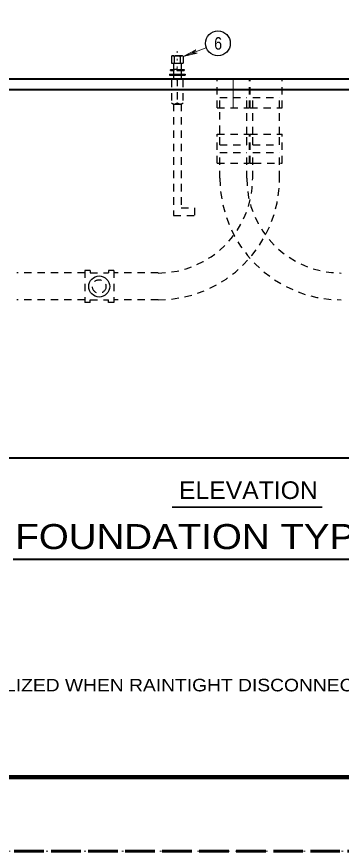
# Model space of a CAD drawing. Extents: x 312583 to 312854, y 144419 to 144597.
# Drawn here: x 312746.6 to 312766.3, y 144418.6 to 144469.3 of the extents above; entities that cross this region are included whole.
import ezdxf
from ezdxf.enums import TextEntityAlignment as Align

# ---------------------------------------------------------------- set-up
doc = ezdxf.new("R2010")
doc.units = 0
doc.header["$LTSCALE"] = 0.3
for name, pattern in [('DOTTED', [1.5, 0.3, -1.2]), ('LONG_DASHED', [7.5, 6, -1.5]), ('SHORT_DASHED', [2.7, 1.5, -1.2])]:
    doc.linetypes.add(name, pattern=pattern)
for name, color, linetype, lineweight in [('1', 7, 'Continuous', 25), ('2', 7, 'Continuous', 13), ('63', 7, 'DOTTED', 13)]:
    doc.layers.add(name, color=color, linetype=linetype, lineweight=lineweight)

msp = doc.modelspace()

# ---------------------------------------------------------------- linework, layer by layer
at = {"layer": '1', "linetype": 'DOTTED', "lineweight": 13}
msp.add_line((312756.3646, 144467.1658), (312756.3646, 144465.4868), dxfattribs=at)
at = {"layer": '1'}
for p, q in [((312756.0042, 144466.8438), (312756.0042, 144466.4451)), ((312756.0962, 144466.8975), (312756.6329, 144466.8975)), ((312756.1806, 144466.8438), (312756.1806, 144466.4451)), ((312756.5409, 144466.8438), (312756.5409, 144466.4451)), ((312756.7249, 144466.8438), (312756.7249, 144466.4451)), ((312755.9506, 144466.0541), (312755.9506, 144465.9928)), ((312756.0042, 144466.4451), (312756.7249, 144466.4451)), ((312756.1269, 144466.4451), (312756.1269, 144465.4868)), ((312756.3262, 144465.9928), (312756.7786, 144465.9928)), ((312756.3492, 144466.0541), (312756.7786, 144466.0541)), ((312756.6022, 144466.4451), (312756.6022, 144465.4868)), ((312756.7786, 144466.0541), (312756.7786, 144465.9928)), ((312755.8892, 144465.7705), (312756.8322, 144465.7705)), ((312755.8892, 144465.7705), (312755.8892, 144465.7168)), ((312755.8892, 144465.7551), (312756.8322, 144465.7551)), ((312755.8892, 144465.7398), (312756.8322, 144465.7398)), ((312755.8892, 144465.7245), (312756.8322, 144465.7245)), ((312755.8892, 144465.7168), (312756.8322, 144465.7168)), ((312756.1269, 144465.4868), (312756.6022, 144465.4868)), ((312756.1882, 144465.4868), (312756.5409, 144465.4868)), ((312756.8322, 144465.7705), (312756.8322, 144465.7168))]:
    msp.add_line(p, q, dxfattribs=at)
at = {"layer": '1', "lineweight": 40}
for p, q in [((312724.8622, 144465.4868), (312790.0289, 144465.4868)), ((312728.8566, 144465.4868), (312794.0232, 144465.4868)), ((312744.5732, 144464.8505), (312772.1962, 144464.8505)), ((312728.2202, 144442.4868), (312794.6672, 144442.4868))]:
    msp.add_line(p, q, dxfattribs=at)
at = {"layer": '1', "linetype": 'SHORT_DASHED'}
for p, q in [((312756.3646, 144465.4868), (312756.3646, 144463.9611)), ((312758.7872, 144463.7311), (312758.7872, 144465.4868)), ((312760.7422, 144463.7311), (312760.7422, 144465.4868)), ((312760.7882, 144463.7311), (312760.7882, 144465.4868)), ((312762.7356, 144463.7311), (312762.7356, 144465.4868)), ((312756.0119, 144465.4255), (312756.0119, 144464.0225)), ((312756.7096, 144465.4255), (312756.7096, 144464.0225)), ((312756.1269, 144463.9688), (312756.1269, 144457.1838)), ((312756.1882, 144463.9611), (312756.5409, 144463.9611)), ((312756.6022, 144463.9688), (312756.6022, 144457.6591)), ((312758.9482, 144464.3675), (312760.5812, 144464.3675)), ((312758.9482, 144463.7311), (312758.9482, 144464.3675)), ((312760.5812, 144463.7311), (312760.5812, 144464.3675)), ((312760.9492, 144464.3675), (312762.5746, 144464.3675)), ((312760.9492, 144463.7311), (312760.9492, 144464.3675)), ((312762.5746, 144463.7311), (312762.5746, 144464.3675)), ((312758.7872, 144463.7311), (312760.7422, 144463.7311)), ((312760.5812, 144462.1365), (312760.5812, 144463.7311)), ((312760.7882, 144463.7311), (312762.7356, 144463.7311)), ((312760.9492, 144462.1365), (312760.9492, 144463.7311)), ((312762.5746, 144462.1365), (312762.5746, 144463.7311)), ((312758.7872, 144460.3731), (312758.7872, 144462.1365)), ((312758.7872, 144462.1365), (312760.7422, 144462.1365)), ((312758.9482, 144461.4925), (312758.9482, 144462.1365)), ((312760.5812, 144461.4925), (312760.5812, 144462.1365)), ((312760.7422, 144460.3731), (312760.7422, 144462.1365)), ((312760.7422, 144462.1058), (312760.7422, 144462.1365)), ((312760.7882, 144460.3731), (312760.7882, 144462.1365)), ((312760.7882, 144462.1365), (312762.7356, 144462.1365)), ((312760.9492, 144461.4925), (312760.9492, 144462.1365)), ((312762.5746, 144461.4925), (312762.5746, 144462.1365)), ((312758.9482, 144461.4925), (312760.5812, 144461.4925)), ((312760.9492, 144461.4925), (312762.5746, 144461.4925)), ((312758.9482, 144461.0171), (312760.5812, 144461.0171)), ((312758.9482, 144459.4531), (312758.9482, 144461.0171)), ((312760.5812, 144459.4531), (312760.5812, 144461.0171)), ((312760.9492, 144461.0171), (312762.5746, 144461.0171)), ((312760.9492, 144459.4531), (312760.9492, 144461.0171)), ((312762.5746, 144459.4531), (312762.5746, 144461.0171)), ((312758.7872, 144460.3731), (312760.7422, 144460.3731)), ((312756.1269, 144457.1838), (312757.3996, 144457.1838)), ((312750.7526, 144453.8565), (312750.7526, 144451.9091)), ((312751.0746, 144453.8565), (312750.7526, 144453.8565)), ((312751.0746, 144453.8565), (312751.0746, 144453.7031)), ((312752.1862, 144453.8565), (312752.1862, 144453.7031)), ((312752.5082, 144453.8565), (312752.1862, 144453.8565)), ((312752.5082, 144453.8565), (312752.5082, 144451.9091)), ((312750.7526, 144453.7031), (312746.6049, 144453.7031)), ((312751.0746, 144453.7031), (312752.1862, 144453.7031)), ((312755.1992, 144453.7031), (312752.5082, 144453.7031)), ((312750.7526, 144452.0701), (312746.6049, 144452.0701)), ((312751.0746, 144451.9091), (312750.7526, 144451.9091)), ((312751.0746, 144451.9091), (312751.0746, 144452.0701)), ((312751.0746, 144452.0701), (312752.1862, 144452.0701)), ((312752.1862, 144451.9091), (312752.1862, 144452.0701)), ((312752.5082, 144451.9091), (312752.1862, 144451.9091)), ((312755.1992, 144452.0701), (312752.5082, 144452.0701))]:
    msp.add_line(p, q, dxfattribs=at)
at = {"layer": '1', "lineweight": 158}
msp.add_line((312616.5, 144423.0846), (312849, 144423.0846), dxfattribs=at)
at = {"layer": '1', "linetype": 'LONG_DASHED', "lineweight": 60}
msp.add_line((312851.75, 144418.5846), (312583.526, 144418.5846), dxfattribs=at)
at = {"layer": '1'}
for points in [[(312756.1192, 144466.8975), (312756.3186, 144466.8975), (312756.2802, 144466.8898), (312756.2572, 144466.8821), (312756.2266, 144466.8668), (312756.1882, 144466.8438), (312756.1729, 144466.8668), (312756.1576, 144466.8821), (312756.1269, 144466.8975), (312756.3032, 144466.8975), (312756.2496, 144466.8821), (312756.2112, 144466.8668), (312756.1882, 144466.8515), (312756.1576, 144466.8745), (312756.1346, 144466.8898), (312756.2802, 144466.8898), (312756.2266, 144466.8745), (312756.1882, 144466.8515), (312756.1499, 144466.8898), (312756.2649, 144466.8898), (312756.1882, 144466.8591), (312756.1576, 144466.8898), (312756.2496, 144466.8898), (312756.1806, 144466.8668), (312756.1652, 144466.8821), (312756.2342, 144466.8821), (312756.1882, 144466.8668), (312756.1729, 144466.8821), (312756.2189, 144466.8821), (312756.1882, 144466.8745), (312756.1806, 144466.8821), (312756.2036, 144466.8821), (312756.1882, 144466.8745)], [(312756.6099, 144466.8975), (312756.4106, 144466.8975), (312756.4412, 144466.8898), (312756.4642, 144466.8821), (312756.5026, 144466.8668), (312756.5409, 144466.8438), (312756.5562, 144466.8668), (312756.5716, 144466.8821), (312756.6022, 144466.8975), (312756.4259, 144466.8975), (312756.4719, 144466.8821), (312756.5102, 144466.8668), (312756.5409, 144466.8515), (312756.5716, 144466.8745), (312756.5869, 144466.8898), (312756.4489, 144466.8898), (312756.4949, 144466.8745), (312756.5409, 144466.8515), (312756.5792, 144466.8898), (312756.4642, 144466.8898), (312756.5409, 144466.8591), (312756.5716, 144466.8898), (312756.4719, 144466.8898), (312756.5409, 144466.8668), (312756.5639, 144466.8821), (312756.4872, 144466.8821), (312756.5409, 144466.8668), (312756.5562, 144466.8821), (312756.5102, 144466.8821), (312756.5409, 144466.8745), (312756.5486, 144466.8821), (312756.5256, 144466.8821), (312756.5409, 144466.8745)], [(312755.9506, 144466.0541), (312756.3646, 144466.1078), (312756.3262, 144465.9928)], [(312756.1269, 144465.9928), (312755.9506, 144466.0005), (312755.9582, 144466.0465), (312756.3492, 144466.1001), (312756.3416, 144466.0541), (312756.1192, 144466.0235), (312756.1192, 144466.0005), (312755.9582, 144466.0081), (312755.9582, 144466.0388), (312756.3416, 144466.0925), (312756.3339, 144466.0618), (312756.1116, 144466.0235), (312756.1116, 144466.0081), (312755.9659, 144466.0158), (312755.9659, 144466.0311), (312756.3262, 144466.0848), (312756.3262, 144466.0695), (312756.1116, 144466.0311), (312756.1039, 144466.0235), (312756.0579, 144466.0158), (312755.9736, 144466.0235), (312756.3186, 144466.0771), (312756.0272, 144466.0235)], [(312756.3492, 144466.0541), (312755.9506, 144465.9928), (312756.1269, 144465.9928)], [(312756.3416, 144466.0005), (312756.7709, 144466.0005), (312756.7709, 144466.0465), (312756.3492, 144466.0465), (312756.3416, 144466.0081), (312756.7632, 144466.0081), (312756.7632, 144466.0388), (312756.3569, 144466.0311), (312756.3492, 144466.0158), (312756.7556, 144466.0158), (312756.7479, 144466.0311), (312756.7479, 144466.0311), (312756.3569, 144466.0311), (312756.3569, 144466.0235), (312756.7479, 144466.0235)]]:
    msp.add_lwpolyline(points, dxfattribs=at)
at = {"layer": '1', "linetype": 'SHORT_DASHED'}
for points in [[(312756.2342, 144465.4868), (312756.4949, 144465.4868), (312756.4642, 144465.4791), (312756.4336, 144465.4715), (312756.4106, 144465.4561), (312756.3876, 144465.4485), (312756.3646, 144465.4331), (312756.3646, 144465.4255), (312756.3186, 144465.4638), (312756.2726, 144465.4791), (312756.2496, 144465.4868), (312756.4719, 144465.4868), (312756.4566, 144465.4791), (312756.4336, 144465.4791), (312756.4106, 144465.4638), (312756.3799, 144465.4485), (312756.3722, 144465.4408), (312756.3646, 144465.4331), (312756.3186, 144465.4638), (312756.2726, 144465.4791), (312756.4412, 144465.4791), (312756.4029, 144465.4638), (312756.3646, 144465.4408), (312756.2879, 144465.4791), (312756.4259, 144465.4791), (312756.3646, 144465.4408), (312756.3032, 144465.4715), (312756.4106, 144465.4791), (312756.3646, 144465.4485), (312756.3262, 144465.4715), (312756.3952, 144465.4715), (312756.3646, 144465.4638), (312756.3262, 144465.4715), (312756.3492, 144465.4561), (312756.3569, 144465.4715), (312756.3569, 144465.4485), (312756.3799, 144465.4638), (312756.3876, 144465.4638), (312756.3952, 144465.4715)], [(312756.2342, 144463.9611), (312756.4949, 144463.9611), (312756.4642, 144463.9688), (312756.4336, 144463.9765), (312756.4106, 144463.9918), (312756.3876, 144463.9995), (312756.3646, 144464.0148), (312756.3646, 144464.0225), (312756.3186, 144463.9841), (312756.2726, 144463.9688), (312756.2496, 144463.9688), (312756.4719, 144463.9611), (312756.4566, 144463.9688), (312756.4336, 144463.9688), (312756.4106, 144463.9841), (312756.3799, 144463.9995), (312756.3722, 144464.0071), (312756.3646, 144464.0148), (312756.3186, 144463.9841), (312756.2726, 144463.9688), (312756.4412, 144463.9688), (312756.4029, 144463.9841), (312756.3646, 144464.0071), (312756.2879, 144463.9688), (312756.4259, 144463.9688), (312756.3646, 144464.0071), (312756.3032, 144463.9765), (312756.4106, 144463.9688), (312756.3646, 144463.9995), (312756.3262, 144463.9765), (312756.3952, 144463.9765), (312756.3646, 144463.9841), (312756.3262, 144463.9841), (312756.3492, 144463.9918), (312756.3569, 144463.9765), (312756.3569, 144463.9995), (312756.3799, 144463.9841), (312756.3876, 144463.9841), (312756.3952, 144463.9765)], [(312758.9482, 144462.1365), (312758.9482, 144462.2131), (312758.9482, 144463.7311)], [(312760.7882, 144460.3731), (312761.0106, 144460.3731), (312762.7356, 144460.3731), (312762.7356, 144462.1365)], [(312756.6022, 144457.6591), (312757.3996, 144457.6591), (312757.3996, 144457.1838)]]:
    msp.add_lwpolyline(points, dxfattribs=at)
at = {"layer": '1'}
msp.add_circle((312751.6189, 144452.8815), 0.6389, dxfattribs=at)
at = {"layer": '1', "linetype": 'SHORT_DASHED'}
msp.add_circle((312751.6189, 144452.8815), 0.4108, dxfattribs=at)
at = {"layer": '1'}
for centre, radius, start, end in [((312756.094, 144466.7979), 0.0993, 25.60064, 154.39936), ((312756.3627, 144466.5846), 0.3126, 55.04559, 124.95441), ((312756.6313, 144466.7979), 0.0993, 25.60064, 154.39936)]:
    msp.add_arc(centre, radius, start, end, dxfattribs=at)
at = {"layer": '1', "linetype": 'SHORT_DASHED'}
for centre, radius, start, end in [((312756.1878, 144465.2153), 0.272, 50.00693, 129.99306), ((312756.5374, 144465.2153), 0.272, 50.00694, 129.99307), ((312756.1878, 144464.2327), 0.272, 230.00694, 309.99307), ((312756.5374, 144464.2327), 0.272, 230.00693, 309.99306), ((312755.1973, 144459.4499), 5.75, 270, 0), ((312755.1973, 144459.4499), 7.3792, 270, 0), ((312766.3293, 144459.4499), 7.3792, 180, 270), ((312766.3293, 144459.4499), 5.75, 180, 270)]:
    msp.add_arc(centre, radius, start, end, dxfattribs=at)
at = {"layer": '2'}
for p, q in [((312758.1279, 144467.3805), (312756.7249, 144466.8438)), ((312756.7249, 144466.8438), (312757.4916, 144467.2501)), ((312756.7249, 144466.8438), (312757.5682, 144467.0508)), ((312757.4916, 144467.2501), (312757.2692, 144467.0508)), ((312757.5682, 144467.0508), (312757.2692, 144467.0508)), ((312759.7686, 144463.7311), (312759.7686, 144465.4868))]:
    msp.add_line(p, q, dxfattribs=at)
at = {"layer": '2', "lineweight": 35}
msp.add_line((312756.0473, 144439.4857), (312765.163, 144439.4857), dxfattribs=at)
at = {"layer": '2', "lineweight": 40}
msp.add_line((312746.3902, 144436.3151), (312777.4709, 144436.3151), dxfattribs=at)
at = {"layer": '2', "lineweight": 25}
msp.add_circle((312758.83, 144467.6462), 0.7557, dxfattribs=at)
at = {"layer": '63'}
msp.add_lwpolyline([(312601.2, 144418.5846), (312853.5, 144418.5846), (312853.5, 144596.7846)], dxfattribs=at)

# ---------------------------------------------------------------- texts
at = {"layer": '2'}
for s, width, p in [('6', 0.85, (312758.6039, 144467.2627)), ('MUST BE UTILIZED WHEN RAINTIGHT DISCONNECT IS REQUIRED', 1.15, (312738.4984, 144428.2971))]:
    msp.add_text(s, height=0.76, dxfattribs=dict(at, width=width)).set_placement(p)
for s, height, width, p in [('ELEVATION', 1.07, 1.05, (312760.6828, 144439.9798)), ('FOUNDATION TYPE "2M-MC"', 1.52, 1.15, (312762.6103, 144436.9361))]:
    msp.add_text(s, height=height, dxfattribs=dict(at, width=width)).set_placement(p, align=Align.CENTER)

doc.saveas('drawing.dxf')
